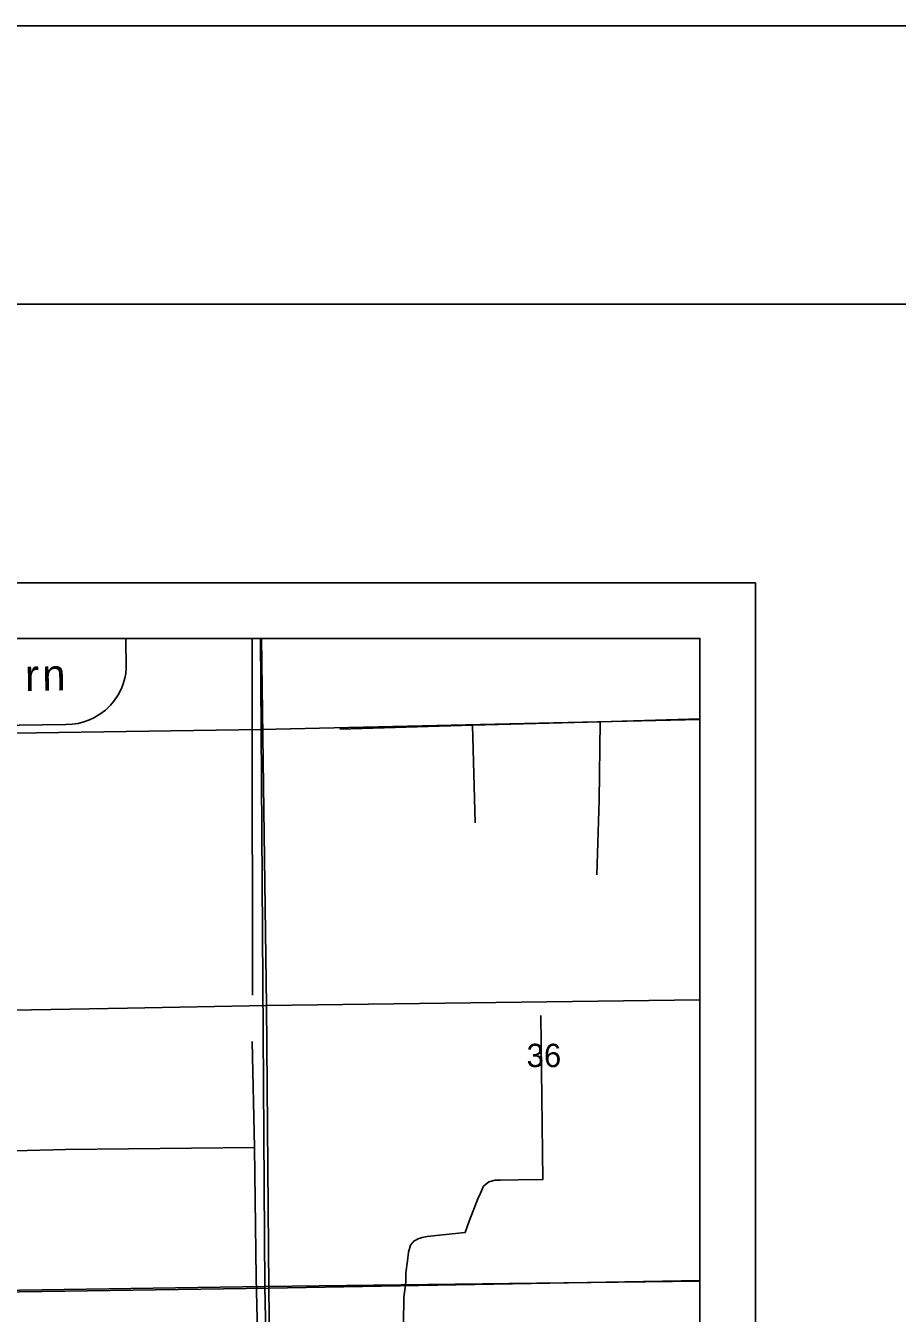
# Model space of a CAD drawing. Extents: x 0 to 40.2, y 0 to 22.
# Drawn here: x 7.69 to 9.254, y 19.689 to 22 of the extents above; entities that cross this region are included whole.
import ezdxf

# ---------------------------------------------------------------- set-up
doc = ezdxf.new("R2010")
doc.units = 0
for name, color, linetype in [('GM_X_Adjacent_County', 7, 'Continuous'), ('GM_X_City_Street', 7, 'Continuous'), ('GM_X_Corporation', 7, 'Continuous'), ('GM_X_County', 7, 'Continuous'), ('GM_X_Major_Lake_Text', 7, 'Continuous'), ('GM_X_Major_River', 7, 'Continuous'), ('GM_X_Minor_Lake', 7, 'Continuous'), ('GM_X_Township', 7, 'Continuous'), ('GM_X_Township_Road', 7, 'Continuous'), ('GM_X_US_Route', 7, 'Continuous')]:
    doc.layers.add(name, color=color, linetype=linetype)

msp = doc.modelspace()

# ---------------------------------------------------------------- linework, layer by layer
at = {"layer": 'GM_X_Adjacent_County'}
for p, q in [((2, 21), (9, 21)), ((9, 21), (9, 14)), ((2.1, 20.9), (8.9, 20.9)), ((8.9, 20.9), (8.9, 14.1))]:
    msp.add_line(p, q, dxfattribs=at)
at = {"layer": 'GM_X_Corporation'}
for points in [[(8.9, 17.4415), (8.9, 20.9), (2.1, 20.9)], [(8.9, 17.4415), (8.9, 20.9), (5.588, 20.9), (5.5927, 20.6995), (6.0382, 20.7021), (5.9919, 20.6239), (5.9538, 20.5583), (5.9235, 20.5032), (5.9081, 20.4755), (5.8909, 20.4334), (5.8744, 20.387), (5.8506, 20.3189), (5.844, 20.2921), (5.8399, 20.2611), (5.8375, 20.216), (5.6046, 20.2128), (5.5342, 20.1328), (5.1717, 19.759), (5.1165, 19.6915), (4.8372, 19.4112)], [(8.9, 17.4415), (8.9, 20.9), (5.588, 20.9)]]:
    msp.add_lwpolyline(points, dxfattribs=at)
for points in [[(8.1108, 20.9), (7.1017, 20.9), (7.1025, 20.7217), (8.112, 20.7367)], [(8.9, 20.7545), (8.9, 20.9), (8.1108, 20.9), (8.112, 20.7367)], [(8.112, 20.7367), (8.1191, 19.7363), (7.1172, 19.7217), (7.1025, 20.7217)], [(8.9, 19.7459), (8.9, 20.7545), (8.112, 20.7367), (8.1191, 19.7363)], [(8.9, 18.743), (8.9, 19.7459), (8.1191, 19.7363), (8.1398, 18.7316)], [(7.1172, 19.7217), (8.1191, 19.7363), (8.1398, 18.7316), (7.1352, 18.7174)]]:
    msp.add_lwpolyline(points, close=True, dxfattribs=at)
at = {"layer": 'GM_X_County'}
msp.add_lwpolyline([(0, 0), (34, 0), (34, 22), (0, 22)], close=True, dxfattribs=at)
at = {"layer": 'GM_X_Major_Lake_Text'}
for p, q in [((8.1218, 20.2409), (8.1131, 20.9)), ((8.1259, 19.7333), (8.9, 19.7471)), ((7.6073, 19.7261), (8.1259, 19.7333))]:
    msp.add_line(p, q, dxfattribs=at)
for points in [[(7.8724, 20.2365), (8.1218, 20.2409), (8.9, 20.2512)], [(6.1106, 20.2085), (7.1141, 20.2231), (7.8724, 20.2365)], [(8.1425, 18.8039), (8.1323, 19.1846), (8.1323, 19.2365), (8.1259, 19.7333), (8.1218, 20.2409)]]:
    msp.add_lwpolyline(points, dxfattribs=at)
at = {"layer": 'GM_X_Major_River'}
msp.add_lwpolyline([(7.3866, 20.74), (7.7618, 20.7457), (7.7731, 20.7462), (7.784, 20.7475), (7.7939, 20.7503), (7.8041, 20.7538), (7.8119, 20.7572), (7.8229, 20.7642), (7.8327, 20.7715), (7.8415, 20.7802), (7.8477, 20.7873), (7.8554, 20.799), (7.8613, 20.8101), (7.8647, 20.8186), (7.8676, 20.8285), (7.8694, 20.8369), (7.8702, 20.8453), (7.8696, 20.9)], dxfattribs=at)
at = {"layer": 'GM_X_Minor_Lake'}
for points in [[(8.0961, 20.9), (8.0964, 20.8687), (8.0961, 20.6435), (8.0967, 20.3796), (8.097, 20.2596)], [(8.9, 20.756), (8.7212, 20.7504), (8.4917, 20.7442), (8.2537, 20.737)], [(8.4917, 20.7442), (8.4965, 20.5691)], [(8.7212, 20.7504), (8.719, 20.6099), (8.7149, 20.4755)], [(8.6146, 20.2233), (8.6178, 19.9286), (8.5739, 19.9281), (8.5417, 19.9275), (8.5322, 19.9272), (8.5208, 19.9247), (8.5116, 19.9165), (8.5061, 19.904), (8.5015, 19.8942), (8.4858, 19.8538), (8.4783, 19.8338), (8.4267, 19.8281), (8.4104, 19.8264), (8.4013, 19.8247), (8.3941, 19.8221), (8.3861, 19.818), (8.3803, 19.8109), (8.3767, 19.7984), (8.375, 19.7829), (8.372, 19.7609), (8.3718, 19.7442), (8.3684, 19.7169), (8.3683, 19.7067), (8.3672, 19.6551)], [(8.0962, 20.1764), (8.1001, 19.9862), (8.1034, 19.7522), (8.108, 19.5562), (8.1121, 19.2984), (8.1158, 19.1533), (8.1226, 18.9789), (8.1246, 18.7636), (8.1286, 18.5878), (8.1329, 18.423)], [(8.1001, 19.9862), (7.7608, 19.9826), (7.5304, 19.9764), (7.3145, 19.9738), (7.1554, 19.9696)]]:
    msp.add_lwpolyline(points, dxfattribs=at)
at = {"layer": 'GM_X_Township'}
msp.add_lwpolyline([(1.5, 21.5), (33.5, 21.5), (33.5, 0.5), (1.5, 0.5)], close=True, dxfattribs=at)
at = {"layer": 'GM_X_Township_Road'}
msp.add_lwpolyline([(2.1, 20.9), (8.9, 20.9), (8.9, 14.1), (2.1, 14.1)], close=True, dxfattribs=at)

# ---------------------------------------------------------------- texts
at = {"layer": 'GM_X_City_Street'}
msp.add_text('36', height=0.04186, rotation=0, dxfattribs=at).set_placement((8.5888, 20.1305))
at = {"layer": 'GM_X_US_Route'}
for s, rotation, p in [('r', 0.833, (7.6886, 20.8056)), ('n', 0.8313, (7.7195, 20.8061))]:
    msp.add_text(s, height=0.0566, rotation=rotation, dxfattribs=at).set_placement(p)

doc.saveas('drawing.dxf')
